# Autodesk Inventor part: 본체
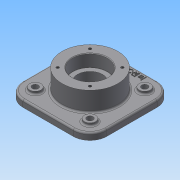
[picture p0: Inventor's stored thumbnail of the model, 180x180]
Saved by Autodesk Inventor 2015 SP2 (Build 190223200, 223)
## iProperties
Created: 2015-07
Part Number: 본체
Material: 일반
Document SubType Name: Modeling
Designer: AMC
Density: 1 g/cm^3
Appearance: 기본값
Mass: 515.417 g
Surface Area: 782.713 cm^2
Volume: 515.417 cm^3
Author: AMC
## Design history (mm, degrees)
sketch "스케치1"
  geometry: L1 (-75, -75)-(75, -75); L2 (75, -75)-(75, 75); L3 (75, 75)-(-75, 75); L4 (-75, 75)-(-75, -75); L5 (-75, -75)-(75, 75); L6 (75, -75)-(-75, 75); 1 further point
  constraints: 12 end point, 2 midpoint, 2 parallel, 1 horizontal, 1 perpendicular
  dimensions: "d0" = 150 distance of L3.end L2.end; "d1" = 150 distance of L2.end L1.end
extrude "돌출1" new body sketch "스케치1" distance "d2" = 12; taper "d3" = 0 deg
sketch "스케치2"
  geometry: C1 r 50 at (0, 0); 1 further point
  constraints: 1 centre point, 1 coincident
  dimensions: "d4" = 100 diameter of C1
extrude "돌출2" join sketch "스케치2" distance "d5" = 47; taper "d7" = 0 deg; dims "d6" = 23, "d8" = 0
sketch "스케치3"
  geometry: L1 (75, 75)-(-75, 75) reference; L2 (-75, 75)-(-75, -75) reference; L3 (75, -75)-(75, 75) reference; L4 (-75, -75)-(75, -75) reference; L5 (-49, -49)-(-49, 49); L6 (-49, 49)-(49, 49); L7 (49, 49)-(49, -49); L8 (49, -49)-(-49, -49); C1 r 10 at (-49, 49); C2 r 10 at (49, 49); C3 r 10 at (49, -49); C4 r 10 at (-49, -49); 1 further point
  constraints: 8 end point, 4 centre point, 4 coincident, 3 other
  dimensions: "d9" = 26 distance between parallel lines of L2 L5; "d10" = 20 diameter of C1; "d11" = 20 diameter of C2; "d12" = 20 diameter of C3; "d13" = 20 diameter of C4
extrude "돌출3" join sketch "스케치3" distance "d14" = 5; taper "d15" = 0 deg
hole "구멍5" diameter "d54" = 45; stored, may be unused: countersink angle "d58" = 90 deg, drill point angle "d60" = 0 deg; dims "d52" = 10, "d53" = 10, "d55" = 6, "d56" = 62, "d57" = 22, "d59" = 8
hole "구멍6" diameter "d63" = 45; stored, may be unused: countersink angle "d67" = 90 deg, drill point angle "d69" = 0 deg; dims "d61" = 10, "d62" = 10, "d64" = 6, "d65" = 62, "d66" = 22, "d68" = 8
sketch "스케치4"
  geometry: L1 (0, 0)-(41, 0); L2 (0, 0)-(28.991, 28.991); A1 r 41 centre (0, 0) between (41, 0) and (28.991, 28.991); 1 further point
  constraints: 4 end point, 2 point on circle, 1 centre point, 1 coincident, 1 horizontal
  dimensions: "d70" = 82 diameter of A1; "d71" = 45 deg angle of L1 L2
hole "구멍7" sketch "스케치4" at (28.991, 28.991) diameter "d72" = 4.917; stored, may be unused: countersink angle "d76" = 90 deg, drill point angle "d78" = 118 deg; dims "d73" = 10, "d74" = 62, "d75" = 22, "d77" = 13
sketch "스케치5"
  geometry: L1 (0, 0)-(41, 0); L2 (0, 0)-(28.991, 28.991); A1 r 41 centre (0, 0) between (28.991, 28.991) and (41, 0); 1 further point
  constraints: 4 end point, 2 point on circle, 1 centre point, 1 coincident, 1 horizontal
  dimensions: "d82" = 82 diameter of A1; "d83" = 45 deg angle of L1 L2
hole "구멍8" sketch "스케치5" at (28.991, 28.991) diameter "d84" = 4.917; stored, may be unused: countersink angle "d88" = 90 deg, drill point angle "d90" = 118 deg; dims "d85" = 10, "d86" = 62, "d87" = 22, "d89" = 13
fillet "모깎기1" dims "d94" = 30
chamfer "모따기1" distance "d95" = 1; stored, may be unused: second distance "d96" = 2, angle "d97" = 45 deg
fillet "모깎기2" dims "d98" = 3
fillet "모깎기3" dims "d99" = 0.3
fillet "모깎기4" dims "d100" = 3
sketch "스케치6"
  geometry: 2 further points
  constraints: 1 vertical alignment, 1 other
  dimensions: "d101" = 65 distance of point (0, 0) point (0, 65)
feature "엠보싱1" sketch "스케치6" dims "d0" = 150, "d1" = 150, "d102" = 1, "d103" = 0
hole "구멍9" diameter "d106" = 11; stored, may be unused: countersink angle "d110" = 90 deg, drill point angle "d112" = 0 deg; dims "d104" = 10, "d105" = 10, "d107" = 6, "d108" = 4, "d109" = 2, "d111" = 8
hole "구멍10" diameter "d115" = 11; stored, may be unused: countersink angle "d119" = 90 deg, drill point angle "d121" = 0 deg; dims "d113" = 10, "d114" = 10, "d116" = 6, "d117" = 4, "d118" = 2, "d120" = 8
hole "구멍11" diameter "d124" = 11; stored, may be unused: countersink angle "d128" = 90 deg, drill point angle "d130" = 0 deg; dims "d122" = 10, "d123" = 10, "d125" = 6, "d126" = 4, "d127" = 2, "d129" = 8
hole "구멍12" diameter "d133" = 11; stored, may be unused: countersink angle "d137" = 90 deg, drill point angle "d139" = 0 deg; dims "d131" = 10, "d132" = 10, "d134" = 6, "d135" = 4, "d136" = 2, "d138" = 8
node "솔리드1"
pattern_circular "원형 패턴1" dims angle "d80" = 360 deg
pattern_circular "원형 패턴2" dims angle "d92" = 360 deg
